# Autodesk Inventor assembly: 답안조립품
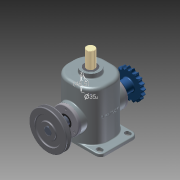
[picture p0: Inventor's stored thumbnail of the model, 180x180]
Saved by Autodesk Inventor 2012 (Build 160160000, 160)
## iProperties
Created: 2014-12
Part Number: 답안조립품
Document SubType Name: Assembly
Designer: Owner
Mass: 8322.91 g
Surface Area: 4222.87 cm^2
Volume: 1869.24 cm^3
Density: 4.45257 g/cm^3
Author: Owner
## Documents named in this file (15)
- C:\Documents and Settings\Owner\바탕 화면\341208V1024\답안조립품.iam
- C:\Documents and Settings\Owner\바탕 화면\341208V1024\본체.ipt
- C:\Documents and Settings\Owner\바탕 화면\341208V1024\커버.ipt
- C:\Documents and Settings\Owner\바탕 화면\341208V1024\M4x0.5.ipt
- C:\Documents and Settings\Owner\바탕 화면\341208V1024\베어링 6205.ipt
- C:\Documents and Settings\Owner\바탕 화면\341208V1024\편심축.ipt
- C:\Documents and Settings\Owner\바탕 화면\341208V1024\오일실.ipt
- C:\Documents and Settings\Owner\바탕 화면\341208V1024\키 8x8.ipt
- C:\Documents and Settings\Owner\바탕 화면\341208V1024\체인 스프로킷.ipt
- C:\Documents and Settings\Owner\바탕 화면\341208V1024\멈춤나사 M5x0.5.ipt
- C:\Documents and Settings\Owner\바탕 화면\341208V1024\멈춤링.ipt
- C:\Documents and Settings\Owner\바탕 화면\341208V1024\V-벨트풀리.ipt
- C:\Documents and Settings\Owner\바탕 화면\341208V1024\부시.ipt
- C:\Documents and Settings\Owner\바탕 화면\341208V1024\슬라이드.ipt
- C:\Documents and Settings\Owner\바탕 화면\341208V1024\스프링1.ipt
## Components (8 placed, 3 different names)
1. 5-체인 스프로킷:1 — 각도:2
2. V-벨트풀리:1 — 각도:4
3. M4x0.5:1
4. M4x0.5:2
5. M4x0.5:3
6. M4x0.5:4
7. M4x0.5:5
8. M4x0.5:6
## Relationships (2: Angle 2)
- 각도:2 [Angle]: 5-체인 스프로킷:1
- 각도:4 [Angle]: V-벨트풀리:1
